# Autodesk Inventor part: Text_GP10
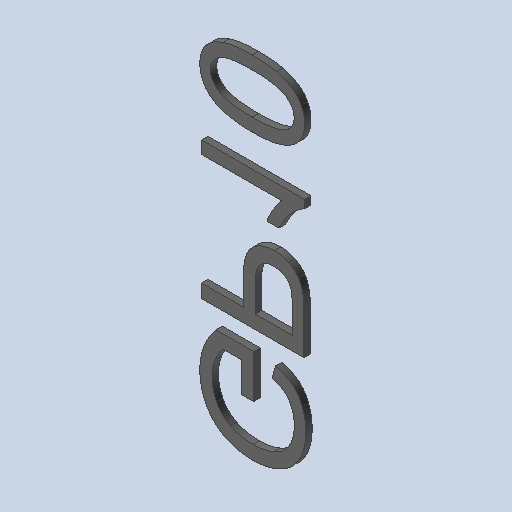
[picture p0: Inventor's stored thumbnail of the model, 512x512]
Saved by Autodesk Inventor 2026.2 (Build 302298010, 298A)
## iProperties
Created: 2026-10
Part Number: Text_GP10
Material: Générique
Document SubType Name: Modeling
Designer: mel
Density: 1 g/cm^3
Appearance: Par défaut
Author: mel
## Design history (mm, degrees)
feature "Base1"
feature "Base2"
feature "Base3"
feature "Base4"
node "Solide1"
node "Solide2"
node "Solide3"
node "Solide4"
